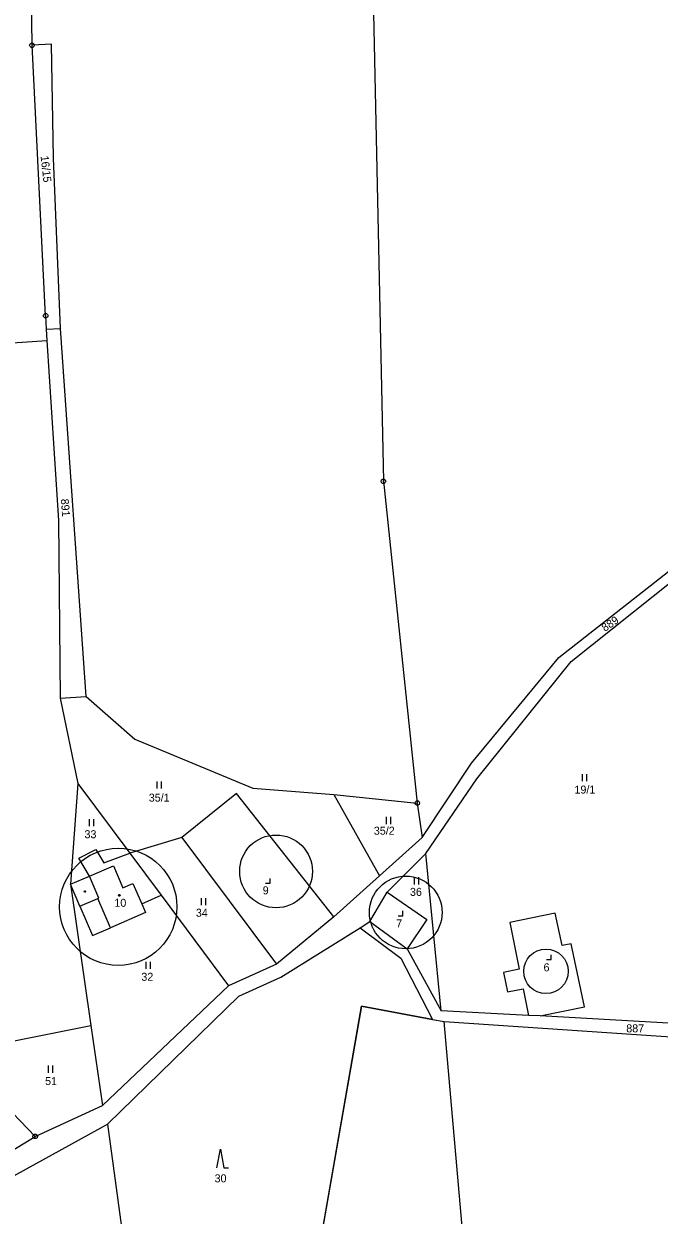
# Model space of a CAD drawing. Extents: x -580551 to -575069, y -1073031 to -1067931.
# Drawn here: x -576638.6 to -576503.8, y -1069267.5 to -1069014.5 of the extents above; entities that cross this region are included whole.
import ezdxf

# ---------------------------------------------------------------- set-up
doc = ezdxf.new("R2010")
doc.units = 0
for name, color, linetype in [('Druh pozemku', 7, 'Continuous'), ('Geodetické body', 7, 'Continuous'), ('Hranice z DKM', 7, 'Continuous'), ('Parcela', 7, 'Continuous'), ('Parcelní číslo', 7, 'Continuous'), ('Parcelní číslo_stavba', 7, 'Continuous'), ('stavební parcely', 7, 'Continuous'), ('Vnitřní kresba', 7, 'Continuous'), ('Vrstva 6', 7, 'Continuous')]:
    doc.layers.add(name, color=color, linetype=linetype)

msp = doc.modelspace()

# ---------------------------------------------------------------- linework, layer by layer
at = {"layer": 'Druh pozemku'}
for p, q in [((-576610.4, -1069175.4), (-576610.4, -1069176.9)), ((-576609.4, -1069176.9), (-576609.4, -1069175.4)), ((-576520.18, -1069173.87), (-576520.18, -1069175.37)), ((-576519.18, -1069175.37), (-576519.18, -1069173.87)), ((-576624.79, -1069183.41), (-576624.79, -1069184.91)), ((-576623.79, -1069184.91), (-576623.79, -1069183.41)), ((-576561.76, -1069182.97), (-576561.76, -1069184.47)), ((-576560.76, -1069184.47), (-576560.76, -1069182.97)), ((-576555.81, -1069195.77), (-576555.81, -1069197.27)), ((-576554.81, -1069197.27), (-576554.81, -1069195.77)), ((-576601.02, -1069200.21), (-576601.02, -1069201.71)), ((-576600.02, -1069201.71), (-576600.02, -1069200.21)), ((-576612.75, -1069213.72), (-576612.75, -1069215.22)), ((-576611.75, -1069215.22), (-576611.75, -1069213.72)), ((-576633.45, -1069235.76), (-576633.45, -1069237.26)), ((-576632.45, -1069237.26), (-576632.45, -1069235.76))]:
    msp.add_line(p, q, dxfattribs=at)
for points in [[(-576587.35, -1069197.02), (-576586.35, -1069197.02), (-576586.35, -1069196.02)], [(-576559.22, -1069203.93), (-576558.22, -1069203.93), (-576558.22, -1069202.93)], [(-576527.75, -1069213.22), (-576526.75, -1069213.22), (-576526.75, -1069212.22)], [(-576597.68, -1069257.5), (-576596.93, -1069253.5), (-576596.18, -1069257.5), (-576595.18, -1069257.5)]]:
    msp.add_lwpolyline(points, dxfattribs=at)
for points in [[(-576625.59, -1069198.65), (-576625.5, -1069198.8), (-576625.59, -1069198.95), (-576625.77, -1069198.95), (-576625.86, -1069198.8), (-576625.77, -1069198.65)], [(-576618.29, -1069199.45), (-576618.2, -1069199.6), (-576618.29, -1069199.75), (-576618.47, -1069199.75), (-576618.56, -1069199.6), (-576618.47, -1069199.45)]]:
    msp.add_lwpolyline(points, close=True, dxfattribs=at)
at = {"layer": 'Geodetické body'}
for p, q in [((-576637.01, -1069019.1), (-576636.77, -1069019.1)), ((-576634.12, -1069076.55), (-576633.88, -1069076.55)), ((-576562.46, -1069111.68), (-576562.22, -1069111.68)), ((-576555.27, -1069180.03), (-576555.03, -1069180.03)), ((-576636.35, -1069250.8), (-576636.11, -1069250.8))]:
    msp.add_line(p, q, dxfattribs=at)
for points in [[(-576636.74, -1069018.62), (-576636.49, -1069018.8), (-576636.39, -1069019.09), (-576636.49, -1069019.38), (-576636.74, -1069019.56), (-576637.05, -1069019.56), (-576637.3, -1069019.38), (-576637.4, -1069019.09), (-576637.3, -1069018.8), (-576637.05, -1069018.62)], [(-576633.85, -1069076.07), (-576633.6, -1069076.25), (-576633.5, -1069076.54), (-576633.6, -1069076.83), (-576633.85, -1069077.01), (-576634.16, -1069077.01), (-576634.41, -1069076.83), (-576634.51, -1069076.54), (-576634.41, -1069076.25), (-576634.16, -1069076.07)], [(-576562.19, -1069111.2), (-576561.94, -1069111.38), (-576561.84, -1069111.67), (-576561.94, -1069111.96), (-576562.19, -1069112.14), (-576562.5, -1069112.14), (-576562.75, -1069111.96), (-576562.85, -1069111.67), (-576562.75, -1069111.38), (-576562.5, -1069111.2)], [(-576555, -1069179.55), (-576554.75, -1069179.73), (-576554.65, -1069180.02), (-576554.75, -1069180.31), (-576555, -1069180.49), (-576555.31, -1069180.49), (-576555.56, -1069180.31), (-576555.66, -1069180.02), (-576555.56, -1069179.73), (-576555.31, -1069179.55)], [(-576636.08, -1069250.32), (-576635.83, -1069250.5), (-576635.73, -1069250.79), (-576635.83, -1069251.08), (-576636.08, -1069251.26), (-576636.39, -1069251.26), (-576636.64, -1069251.08), (-576636.74, -1069250.79), (-576636.64, -1069250.5), (-576636.39, -1069250.32)]]:
    msp.add_lwpolyline(points, close=True, dxfattribs=at)
at = {"layer": 'Hranice z DKM'}
msp.add_lwpolyline([(-576551.9, -1069225.95), (-576567.01, -1069223.17), (-576575.94, -1069274.53), (-576594.44, -1069294.92)], dxfattribs=at)
at = {"layer": 'Parcela'}
for p, q in [((-576636.89, -1069019.1), (-576637.26, -1068990.18)), ((-576564.89, -1068992.94), (-576562.34, -1069111.68)), ((-576634, -1069076.55), (-576636.89, -1069019.1)), ((-576634, -1069076.55), (-576633.89, -1069079.4)), ((-576633.89, -1069079.4), (-576630.86, -1069079.23)), ((-576633.89, -1069079.4), (-576633.74, -1069081.81)), ((-576625.38, -1069157.36), (-576630.86, -1069079.23)), ((-576716.09, -1069087.25), (-576633.74, -1069081.81)), ((-576633.74, -1069081.81), (-576631.31, -1069120.02)), ((-576562.34, -1069111.68), (-576555.15, -1069180.03)), ((-576631.31, -1069120.02), (-576630.94, -1069157.77)), ((-576525.09, -1069149.12), (-576486.85, -1069118.96)), ((-576522.53, -1069149.98), (-576500.56, -1069132.49)), ((-576543.66, -1069171.57), (-576525.09, -1069149.12)), ((-576542.51, -1069174.86), (-576522.53, -1069149.98)), ((-576630.94, -1069157.77), (-576625.38, -1069157.36)), ((-576630.94, -1069157.77), (-576627.17, -1069175.87)), ((-576625.38, -1069157.36), (-576615.07, -1069166.47)), ((-576615.07, -1069166.47), (-576590.07, -1069176.86)), ((-576554.12, -1069187.29), (-576543.66, -1069171.57)), ((-576627.17, -1069175.87), (-576628.74, -1069197.25)), ((-576627.17, -1069175.87), (-576616.17, -1069190.65)), ((-576553.32, -1069190.72), (-576542.51, -1069174.86)), ((-576593.52, -1069177.98), (-576605.09, -1069187.31)), ((-576572.85, -1069204.19), (-576593.52, -1069177.98)), ((-576590.07, -1069176.86), (-576572.85, -1069178.21)), ((-576572.85, -1069178.21), (-576555.15, -1069180.03)), ((-576555.15, -1069180.03), (-576554.12, -1069187.29)), ((-576605.09, -1069187.31), (-576616.17, -1069190.65)), ((-576605.09, -1069187.31), (-576585.04, -1069214.22)), ((-576554.12, -1069187.29), (-576563.17, -1069195.45)), ((-576626.96, -1069191.73), (-576623.32, -1069189.85)), ((-576623.32, -1069189.85), (-576621.67, -1069192.71)), ((-576621.67, -1069192.71), (-576616.17, -1069190.65)), ((-576616.17, -1069190.65), (-576609.52, -1069199.59)), ((-576561.51, -1069198.95), (-576553.32, -1069190.72)), ((-576550.07, -1069224.11), (-576553.32, -1069190.72)), ((-576624.7, -1069195.52), (-576626.96, -1069191.73)), ((-576628.74, -1069197.25), (-576624.7, -1069195.52)), ((-576563.17, -1069195.45), (-576572.85, -1069204.19)), ((-576626.74, -1069201.91), (-576628.74, -1069197.25)), ((-576628.74, -1069197.25), (-576624.42, -1069227.23)), ((-576613.62, -1069201.42), (-576609.52, -1069199.59)), ((-576609.52, -1069199.59), (-576595.2, -1069218.83)), ((-576565.24, -1069205.19), (-576561.51, -1069198.95)), ((-576561.51, -1069198.95), (-576553.14, -1069204.73)), ((-576626.74, -1069201.91), (-576624.03, -1069208.14)), ((-576612.83, -1069203.24), (-576620.27, -1069206.49)), ((-576613.62, -1069201.42), (-576612.83, -1069203.24)), ((-576525.87, -1069203.37), (-576535.55, -1069205.36)), ((-576524.45, -1069210.29), (-576525.87, -1069203.37)), ((-576572.85, -1069204.19), (-576585.04, -1069214.22)), ((-576567.28, -1069206.47), (-576565.24, -1069205.19)), ((-576565.24, -1069205.19), (-576557.33, -1069210.96)), ((-576553.14, -1069204.73), (-576557.33, -1069210.96)), ((-576535.55, -1069205.36), (-576533.51, -1069215.3)), ((-576624.03, -1069208.14), (-576620.27, -1069206.49)), ((-576584.07, -1069216.99), (-576567.28, -1069206.47)), ((-576567.28, -1069206.47), (-576558.68, -1069212.96)), ((-576557.33, -1069210.96), (-576550.07, -1069224.11)), ((-576522.52, -1069209.89), (-576524.45, -1069210.29)), ((-576519.7, -1069223.26), (-576522.52, -1069209.89)), ((-576558.68, -1069212.96), (-576551.9, -1069225.95)), ((-576585.04, -1069214.22), (-576595.2, -1069218.83)), ((-576533.51, -1069215.3), (-576536.84, -1069215.98)), ((-576536.84, -1069215.98), (-576536, -1069220.11)), ((-576595.2, -1069218.83), (-576621.97, -1069244.26)), ((-576593.03, -1069221.02), (-576584.07, -1069216.99)), ((-576620.89, -1069248.16), (-576593.03, -1069221.02)), ((-576536, -1069220.11), (-576532.68, -1069219.44)), ((-576532.68, -1069219.44), (-576531.54, -1069225.09)), ((-576575.94, -1069274.53), (-576567.01, -1069223.17)), ((-576567.01, -1069223.17), (-576551.9, -1069225.95)), ((-576531.54, -1069225.09), (-576550.07, -1069224.11)), ((-576529.05, -1069225.22), (-576519.7, -1069223.26)), ((-576551.9, -1069225.95), (-576549.47, -1069226.4)), ((-576549.47, -1069226.4), (-576475.2, -1069231.41)), ((-576544.49, -1069283.21), (-576549.47, -1069226.4)), ((-576529.05, -1069225.22), (-576531.54, -1069225.09)), ((-576492.8, -1069227.28), (-576529.05, -1069225.22)), ((-576653.31, -1069233.01), (-576624.42, -1069227.23)), ((-576624.42, -1069227.23), (-576621.97, -1069244.26)), ((-576653.31, -1069233.01), (-576636.23, -1069250.8)), ((-576636.23, -1069250.8), (-576621.97, -1069244.26)), ((-576648.32, -1069263.29), (-576620.89, -1069248.16)), ((-576620.89, -1069248.16), (-576613.08, -1069306.06)), ((-576650.61, -1069259.61), (-576636.23, -1069250.8))]:
    msp.add_line(p, q, dxfattribs=at)
at = {"layer": 'stavební parcely'}
for centre, radius in [((-576585.114, -1069194.518), 7.724), ((-576618.59, -1069202.04), 12.447), ((-576557.597, -1069203.24), 7.724), ((-576527.86, -1069215.74), 4.715)]:
    msp.add_circle(centre, radius, dxfattribs=at)
at = {"layer": 'Vnitřní kresba'}
for p, q in [((-576624.7, -1069195.52), (-576619.62, -1069193.32)), ((-576619.62, -1069193.32), (-576617.6, -1069197.98)), ((-576622.72, -1069200.19), (-576624.7, -1069195.52)), ((-576617.6, -1069197.98), (-576615.5, -1069197.08)), ((-576615.5, -1069197.08), (-576613.62, -1069201.42)), ((-576626.74, -1069201.91), (-576622.92, -1069200.27)), ((-576622.92, -1069200.27), (-576622.72, -1069200.19)), ((-576620.27, -1069206.49), (-576622.92, -1069200.27))]:
    msp.add_line(p, q, dxfattribs=at)
at = {"layer": 'Vrstva 6'}
for p, q in [((-576632.76, -1069018.87), (-576636.89, -1069019.1)), ((-576632.31, -1069043.07), (-576632.76, -1069018.87)), ((-576630.86, -1069079.23), (-576632.31, -1069043.07)), ((-576572.85, -1069178.21), (-576563.17, -1069195.45))]:
    msp.add_line(p, q, dxfattribs=at)

# ---------------------------------------------------------------- texts
at = {"layer": 'Parcelní číslo'}
for s, rotation, p in [('16/15', 276.50943, (-576635.088, -1069042.639)), ('891', 274.61867, (-576630.796, -1069115.454)), ('889', 33.68992, (-576515.374, -1069143.683))]:
    msp.add_text(s, height=1.7, rotation=rotation, dxfattribs=at).set_placement(p)
for s, p in [('35/1', (-576612.122, -1069179.71)), ('19/1', (-576521.807, -1069178)), ('33', (-576625.76, -1069187.48)), ('35/2', (-576564.374, -1069186.73)), ('36', (-576556.703, -1069199.72)), ('34', (-576602.133, -1069204.15)), ('32', (-576613.698, -1069217.75)), ('887', (-576510.816, -1069228.7)), ('51', (-576634.12, -1069239.89)), ('30', (-576598.156, -1069260.55))]:
    msp.add_text(s, height=1.7, dxfattribs=at).set_placement(p)
at = {"layer": 'Parcelní číslo_stavba'}
for s, p in [('9', (-576587.948, -1069199.39)), ('10', (-576619.423, -1069202.04)), ('7', (-576559.632, -1069206.41)), ('6', (-576528.368, -1069215.74))]:
    msp.add_text(s, height=1.7, dxfattribs=at).set_placement(p)

doc.saveas('drawing.dxf')
